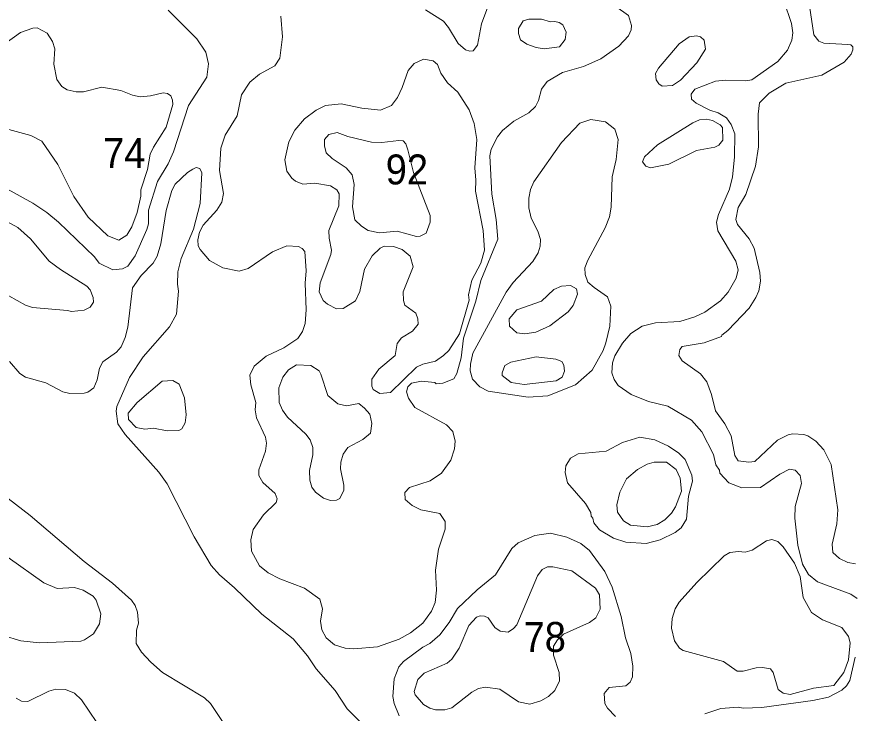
# Model space of a CAD drawing. Extents: x 673.6 to 698.9, y 7012 to 7040.1.
# Drawn here: x 682.608 to 684.841, y 7024.299 to 7026.159 of the extents above; entities that cross this region are included whole.
import ezdxf

# ---------------------------------------------------------------- set-up
doc = ezdxf.new("R2010")
doc.units = 0
doc.header["$LTSCALE"] = 0.032
doc.layers.add('2', color=7, linetype='Continuous', lineweight=13)
doc.layers.add('21', color=7, linetype='Continuous')

msp = doc.modelspace()

# ---------------------------------------------------------------- linework, layer by layer
at = {"layer": '2'}
for points in [[(684.165, 7026.2356), (684.1685, 7026.2173), (684.1927, 7026.1923), (684.2075, 7026.1863), (684.2412, 7026.1626), (684.2493, 7026.1358)], [(683.6996, 7026.1774), (683.7474, 7026.1473), (683.761, 7026.1302), (683.7865, 7026.0876), (683.8056, 7026.0704), (683.8175, 7026.0668), (683.8262, 7026.0681), (683.8384, 7026.0835), (683.8489, 7026.1402), (683.8764, 7026.2147)], [(684.5547, 7025.9879), (684.5703, 7025.9906), (684.6401, 7026.0392), (684.6657, 7026.0694), (684.6776, 7026.0964), (684.6801, 7026.1164), (684.6767, 7026.141), (684.6563, 7026.2012)], [(684.7246, 7026.1881), (684.7361, 7026.1105), (684.7494, 7026.0938), (684.763, 7026.0888), (684.8267, 7026.0847), (684.8345, 7026.0838), (684.8399, 7026.0785), (684.8405, 7026.0703), (684.8358, 7026.0592), (684.8173, 7026.0379), (684.7569, 7026.0031), (684.6608, 7025.9814), (684.6171, 7025.9552), (684.5913, 7025.9291)], [(683.0124, 7026.1763), (683.0891, 7026.1003), (683.1131, 7026.0648), (683.1195, 7026.0329), (683.1156, 7025.9981), (683.0661, 7025.9218), (683.0263, 7025.7982), (683.0122, 7025.7667), (682.9839, 7025.7195), (682.9601, 7025.6424), (682.9593, 7025.6059), (682.9554, 7025.5907), (682.9244, 7025.5205), (682.9047, 7025.4929), (682.8902, 7025.4858), (682.8647, 7025.4835), (682.8284, 7025.5011), (682.8158, 7025.5176), (682.7194, 7025.6106), (682.6879, 7025.6365), (682.6506, 7025.6612), (682.5751, 7025.7032)], [(683.37, 7025.5403), (683.3599, 7025.5456), (683.329, 7025.5473), (683.2904, 7025.5312), (683.2262, 7025.4869), (683.2016, 7025.4793), (683.1585, 7025.4887), (683.1223, 7025.5078), (683.0972, 7025.5373), (683.0926, 7025.547), (683.0916, 7025.5636), (683.0958, 7025.5834), (683.1057, 7025.6026), (683.1419, 7025.6422), (683.1557, 7025.6641), (683.1598, 7025.6871), (683.1492, 7025.7489), (683.1532, 7025.8084), (683.1647, 7025.8429), (683.196, 7025.8942), (683.2078, 7025.9507), (683.2301, 7025.984), (683.256, 7026.0056), (683.2972, 7026.028), (683.3103, 7026.0485), (683.3177, 7026.1058), (683.3134, 7026.161)], [(682.567, 7025.8637), (682.6457, 7025.8423), (682.675, 7025.8268), (682.7173, 7025.7648), (682.7605, 7025.6789), (682.7988, 7025.624), (682.8512, 7025.5741), (682.8801, 7025.5623), (682.902, 7025.5756), (682.9151, 7025.598), (682.9297, 7025.6365), (682.9396, 7025.6802), (682.9388, 7025.697), (682.9571, 7025.751), (682.9644, 7025.7923), (682.9726, 7025.8104), (683.0066, 7025.8645), (683.0243, 7025.9245), (683.0241, 7025.9359), (683.0189, 7025.9481), (683.01, 7025.9542), (682.999, 7025.9559), (682.9646, 7025.9477), (682.9377, 7025.9452), (682.9169, 7025.9497), (682.8854, 7025.9623), (682.8351, 7025.9706), (682.7865, 7025.9583), (682.7663, 7025.9585), (682.7427, 7025.9639), (682.7286, 7025.9731), (682.7152, 7025.9915), (682.707, 7026.0325), (682.7095, 7026.0733), (682.7037, 7026.093), (682.6892, 7026.115), (682.6621, 7026.1291), (682.6512, 7026.1283), (682.6179, 7026.1168), (682.5795, 7026.0896)], [(684.2493, 7026.1358), (684.248, 7026.1244), (684.241, 7026.1084), (684.2153, 7026.0802), (684.1676, 7026.0464), (684.1207, 7026.0262), (684.0654, 7026.01), (684.0243, 7025.9859), (684.0088, 7025.9653), (684.0012, 7025.935), (683.9933, 7025.919), (683.9749, 7025.9024), (683.935, 7025.8806), (683.9047, 7025.855), (683.8918, 7025.8388), (683.8743, 7025.8054), (683.8707, 7025.788), (683.8764, 7025.6854), (683.888, 7025.6174), (683.892, 7025.5649), (683.8466, 7025.4547), (683.8338, 7025.3998), (683.8008, 7025.301), (683.7942, 7025.2484), (683.7831, 7025.2067), (683.7753, 7025.1918), (683.7452, 7025.1805), (683.7279, 7025.1793), (683.7241, 7025.1825), (683.6888, 7025.1858), (683.6622, 7025.1809), (683.6517, 7025.1706), (683.6489, 7025.1573), (683.6535, 7025.1406), (683.6708, 7025.1155), (683.7551, 7025.0697), (683.7719, 7025.0518), (683.7786, 7025.0256), (683.7762, 7025.0054), (683.7668, 7024.9749), (683.7422, 7024.9407), (683.7113, 7024.92), (683.6569, 7024.9018), (683.6437, 7024.8888), (683.6449, 7024.8704), (683.6633, 7024.8536), (683.6864, 7024.8422), (683.7372, 7024.8325), (683.7515, 7024.8116), (683.7514, 7024.7907), (683.7343, 7024.7375), (683.7261, 7024.6813), (683.7285, 7024.628), (683.7247, 7024.5954), (683.7155, 7024.5716), (683.6925, 7024.5402), (683.6592, 7024.5142), (683.6289, 7024.4967), (683.5713, 7024.4769), (683.5076, 7024.471), (683.485, 7024.4734), (683.4564, 7024.4822), (683.4341, 7024.5008), (683.4223, 7024.5223), (683.4188, 7024.5453), (683.4244, 7024.5781), (683.4174, 7024.6037), (683.3759, 7024.6336), (683.3105, 7024.6582), (683.2796, 7024.6742), (683.2563, 7024.6928), (683.2347, 7024.7323), (683.233, 7024.7625), (683.2388, 7024.7901), (683.2671, 7024.8295), (683.3001, 7024.8616), (683.3035, 7024.8717), (683.2982, 7024.8863), (683.2649, 7024.9155), (683.2542, 7024.9338), (683.2544, 7024.9495), (683.2718, 7024.9991), (683.2749, 7025.0205), (683.2724, 7025.0366), (683.2483, 7025.0881), (683.2445, 7025.1096), (683.2461, 7025.1288), (683.233, 7025.1764), (683.2306, 7025.2022), (683.2421, 7025.2263), (683.2735, 7025.2525), (683.3214, 7025.2748), (683.3583, 7025.2997), (683.371, 7025.319), (683.3776, 7025.3404)], [(684.4097, 7025.9389), (684.4082, 7025.9522), (684.4182, 7025.9656), (684.4737, 7025.9872), (684.5002, 7025.9895), (684.5547, 7025.9879)], [(684.8518, 7024.6057), (684.8347, 7024.6171), (684.746, 7024.6505), (684.7215, 7024.6695), (684.7058, 7024.6974), (684.6933, 7024.7483), (684.685, 7024.8199), (684.6864, 7024.8511), (684.7031, 7024.9131), (684.6995, 7024.934), (684.6865, 7024.9481), (684.6709, 7024.9507), (684.6456, 7024.9376), (684.5932, 7024.9024), (684.5434, 7024.9016), (684.509, 7024.9148), (684.4848, 7024.9403), (684.4841, 7024.9485), (684.4747, 7024.9624), (684.4679, 7024.9905), (684.4368, 7025.0511), (684.4092, 7025.0821), (684.3465, 7025.1192), (684.2942, 7025.1315), (684.2481, 7025.1506), (684.2137, 7025.1741), (684.2028, 7025.1905), (684.197, 7025.2085), (684.1986, 7025.2351), (684.2043, 7025.2533), (684.2255, 7025.2875), (684.2471, 7025.3132), (684.2781, 7025.3331), (684.3136, 7025.3419), (684.3784, 7025.3454), (684.4182, 7025.3582), (684.4446, 7025.3704), (684.487, 7025.4004), (684.5071, 7025.4235), (684.5283, 7025.4609), (684.5339, 7025.4837), (684.5273, 7025.506), (684.4796, 7025.5872), (684.4764, 7025.6104), (684.4818, 7025.6312), (684.5107, 7025.6983), (684.519, 7025.7316), (684.5239, 7025.7842), (684.5247, 7025.8465), (684.5157, 7025.8712), (684.5032, 7025.8893), (684.4809, 7025.9026), (684.4587, 7025.9097), (684.4214, 7025.9281), (684.4097, 7025.9389)], [(684.5913, 7025.9291), (684.5873, 7025.8987), (684.588, 7025.8113), (684.5799, 7025.7598), (684.5547, 7025.6846), (684.534, 7025.65)], [(682.589, 7025.2381), (682.6166, 7025.2064), (682.6316, 7025.1968), (682.6852, 7025.1816), (682.7307, 7025.1572), (682.7494, 7025.1533), (682.7876, 7025.1539), (682.7974, 7025.1567), (682.8141, 7025.1682), (682.8225, 7025.1893), (682.8292, 7025.2203), (682.8376, 7025.238), (682.8739, 7025.2632), (682.887, 7025.2773), (682.8978, 7025.3028), (682.9041, 7025.3302), (682.9167, 7025.4349), (682.9405, 7025.4685), (682.9723, 7025.5012), (682.9831, 7025.5196), (682.9922, 7025.5524), (683.0071, 7025.6414), (683.0224, 7025.6955), (683.0311, 7025.7118), (683.064, 7025.7434), (683.0782, 7025.7519), (683.0871, 7025.7561), (683.0969, 7025.7539), (683.102, 7025.742), (683.0974, 7025.6608), (683.0794, 7025.5921), (683.047, 7025.5139), (683.0382, 7025.4781), (683.0367, 7025.4452), (683.0399, 7025.4259), (683.0341, 7025.365), (683.0154, 7025.3308), (682.9451, 7025.2513), (682.9086, 7025.196), (682.8755, 7025.1186), (682.8731, 7025.1058), (682.8781, 7025.0723), (682.8976, 7025.0437), (682.9871, 7024.9429), (683.0094, 7024.9119), (683.0816, 7024.7704), (683.1266, 7024.694), (683.1494, 7024.6686), (683.1895, 7024.6344), (683.2626, 7024.5639), (683.3455, 7024.498), (683.3838, 7024.453), (683.4069, 7024.4178)], [(684.534, 7025.65), (684.528, 7025.6181), (684.5321, 7025.6044), (684.5632, 7025.5657), (684.5769, 7025.5413), (684.5922, 7025.476), (684.5938, 7025.453), (684.5891, 7025.4271), (684.5814, 7025.4094), (684.5631, 7025.3812), (684.5064, 7025.3211), (684.4904, 7025.3091), (684.4898, 7025.3056), (684.4431, 7025.2885), (684.3843, 7025.2786), (684.3781, 7025.2702), (684.3753, 7025.2541), (684.3845, 7025.24), (684.4338, 7025.2052), (684.45, 7025.1842), (684.4629, 7025.1505), (684.4732, 7025.1066), (684.4987, 7025.0721), (684.5155, 7025.0402), (684.5247, 7024.9874), (684.5336, 7024.9737), (684.5621, 7024.9698), (684.5785, 7024.9713), (684.6388, 7025.0286), (684.6675, 7025.0424), (684.6801, 7025.0453), (684.709, 7025.0437), (684.7196, 7025.0402), (684.7409, 7025.0256), (684.7631, 7025.0025), (684.782, 7024.9639), (684.8003, 7024.8423), (684.7977, 7024.8049), (684.7845, 7024.7511), (684.787, 7024.7284), (684.8044, 7024.7122), (684.8271, 7024.7016), (684.8474, 7024.6986)], [(682.5833, 7025.6114), (682.6109, 7025.5967), (682.6449, 7025.5661), (682.6945, 7025.5066), (682.7246, 7025.484), (682.7949, 7025.4397), (682.8039, 7025.4299), (682.8122, 7025.409), (682.8131, 7025.3973), (682.8042, 7025.3835), (682.788, 7025.3757), (682.7543, 7025.3716), (682.7437, 7025.3749), (682.6501, 7025.3823), (682.6312, 7025.3886), (682.5866, 7025.4142)], [(683.3776, 7025.3404), (683.381, 7025.3761), (683.3776, 7025.4474), (683.3808, 7025.481), (683.3769, 7025.532), (683.37, 7025.5403)], [(683.1646, 7024.2666), (683.1256, 7024.3252), (683.1095, 7024.3406), (682.9974, 7024.4078), (682.9657, 7024.4358), (682.9412, 7024.4626), (682.9269, 7024.4851), (682.9273, 7024.5215), (682.933, 7024.5399), (682.9306, 7024.5692), (682.9244, 7024.5866), (682.9143, 7024.6013), (682.8635, 7024.6465), (682.7879, 7024.7049), (682.644, 7024.8273), (682.5846, 7024.8727)], [(684.2063, 7024.2906), (684.185, 7024.3132), (684.1776, 7024.3256), (684.1764, 7024.3521), (684.1895, 7024.368), (684.2343, 7024.3723), (684.2458, 7024.3826), (684.2519, 7024.3961), (684.2527, 7024.4249), (684.2472, 7024.4587), (684.233, 7024.5009), (684.2216, 7024.5575), (684.1974, 7024.6363), (684.1782, 7024.6775), (684.1369, 7024.7339), (684.1142, 7024.7525), (684.0763, 7024.7695), (684.0329, 7024.78), (683.9908, 7024.7739), (683.9465, 7024.754), (683.9294, 7024.739), (683.8857, 7024.6687), (683.8368, 7024.6284), (683.7846, 7024.5788), (683.762, 7024.5413), (683.7373, 7024.5085), (683.7107, 7024.4859), (683.6921, 7024.4756), (683.6403, 7024.4377), (683.628, 7024.4232), (683.616, 7024.3908), (683.6123, 7024.3438), (683.6159, 7024.325), (683.6289, 7024.2922)], [(682.585, 7024.7154), (682.68, 7024.6476), (682.7162, 7024.6328), (682.7618, 7024.6352), (682.7851, 7024.6278), (682.8118, 7024.6116), (682.8202, 7024.6008), (682.8327, 7024.5649), (682.8285, 7024.538), (682.8131, 7024.5112), (682.7887, 7024.4949), (682.7787, 7024.4915), (682.669, 7024.4874), (682.6187, 7024.4924), (682.5721, 7024.5069)], [(684.4448, 7024.2974), (684.4875, 7024.3122), (684.5338, 7024.3154), (684.5475, 7024.3124), (684.5968, 7024.3143), (684.7334, 7024.3329), (684.7748, 7024.3425), (684.8108, 7024.3607), (684.8229, 7024.3724), (684.832, 7024.3871), (684.8461, 7024.4488)], [(683.4069, 7024.4178), (683.4577, 7024.3597), (683.4897, 7024.3113), (683.5591, 7024.2409), (683.5731, 7024.2116), (683.5839, 7024.1784)], [(682.6063, 7024.3393), (682.6205, 7024.3314), (682.6372, 7024.3304), (682.6938, 7024.3586), (682.7125, 7024.3632), (682.7385, 7024.363), (682.7618, 7024.3528), (682.7808, 7024.3348), (682.8218, 7024.2748)]]:
    msp.add_lwpolyline(points, dxfattribs=at)
for points in [[(683.9699, 7026.0858), (683.9532, 7026.0977), (683.9476, 7026.1143), (683.9474, 7026.1281), (683.9599, 7026.1482), (683.975, 7026.153), (684.0092, 7026.153), (684.0332, 7026.1451), (684.0448, 7026.1461), (684.0557, 7026.144), (684.0663, 7026.1379), (684.0744, 7026.1177), (684.0721, 7026.0984), (684.0571, 7026.0784), (684.0156, 7026.0737), (683.9944, 7026.0767)], [(684.3307, 7025.9733), (684.3222, 7025.9795), (684.3147, 7025.9909), (684.3137, 7026.0072), (684.3215, 7026.0215), (684.376, 7026.0871), (684.4034, 7026.1053), (684.4229, 7026.1077), (684.4333, 7026.1057), (684.4436, 7026.0963), (684.4467, 7026.0729), (684.4237, 7026.0356), (684.3801, 7025.9896), (684.3587, 7025.9756)], [(683.5124, 7025.4006), (683.5236, 7025.4252), (683.5363, 7025.4849), (683.5564, 7025.5209), (683.578, 7025.5408), (683.5889, 7025.5464), (683.6135, 7025.5457), (683.6371, 7025.538), (683.6584, 7025.5197), (683.6667, 7025.4911), (683.6398, 7025.4241), (683.6401, 7025.4015), (683.6436, 7025.3892), (683.6733, 7025.3676), (683.6791, 7025.3525), (683.6792, 7025.3382), (683.6642, 7025.3197), (683.6355, 7025.3015), (683.6235, 7025.2866), (683.6182, 7025.2547), (683.5746, 7025.2176), (683.5562, 7025.191), (683.556, 7025.1728), (683.5597, 7025.1635), (683.5773, 7025.1531), (683.6057, 7025.1555), (683.6749, 7025.2234), (683.692, 7025.2317), (683.7259, 7025.2397), (683.7476, 7025.2544), (683.7611, 7025.2678), (683.7903, 7025.312), (683.8155, 7025.4027), (683.8141, 7025.4167), (683.823, 7025.4559), (683.8468, 7025.5015), (683.8567, 7025.536), (683.8534, 7025.5885), (683.8324, 7025.6931), (683.8337, 7025.7224), (683.8305, 7025.7557), (683.8361, 7025.8317), (683.8292, 7025.8744), (683.8158, 7025.9102), (683.7851, 7025.9574), (683.758, 7025.9824), (683.7405, 7026.0085), (683.7312, 7026.0319), (683.7195, 7026.0415), (683.6943, 7026.0454), (683.6686, 7026.0339), (683.6531, 7026.0157), (683.6372, 7025.9698), (683.6241, 7025.9436), (683.6086, 7025.9224), (683.5794, 7025.9098), (683.5292, 7025.9145), (683.4742, 7025.9262), (683.4322, 7025.9217), (683.4074, 7025.9094), (683.3763, 7025.8863), (683.3506, 7025.8565), (683.3342, 7025.8254), (683.3235, 7025.7767), (683.3287, 7025.7471), (683.3421, 7025.7277), (683.3517, 7025.7198), (683.3714, 7025.7118), (683.4039, 7025.715), (683.4455, 7025.7077), (683.4626, 7025.6966), (683.4687, 7025.6861), (683.468, 7025.6543), (683.441, 7025.5885), (683.4417, 7025.5675), (683.4482, 7025.5359), (683.4466, 7025.5243), (683.4183, 7025.4483), (683.4155, 7025.4242), (683.4259, 7025.4014), (683.4375, 7025.3917), (683.4618, 7025.379), (683.4795, 7025.3801)], [(684.1109, 7025.8753), (684.1403, 7025.885), (684.1802, 7025.8787), (684.2044, 7025.8592), (684.2133, 7025.8317), (684.2084, 7025.7775), (684.1976, 7025.732), (684.1952, 7025.6502), (684.1903, 7025.6247), (684.1789, 7025.5952), (684.1325, 7025.509), (684.1247, 7025.4882), (684.1254, 7025.4705), (684.133, 7025.4507), (684.1494, 7025.4358), (684.1853, 7025.4115), (684.1936, 7025.3863), (684.1912, 7025.3325), (684.1811, 7025.2882), (684.1731, 7025.2679), (684.1443, 7025.2153), (684.0997, 7025.1762), (684.0257, 7025.1464), (683.9731, 7025.1432), (683.8667, 7025.1589), (683.8439, 7025.1705), (683.8248, 7025.1916), (683.8181, 7025.2133), (683.819, 7025.2318), (683.8259, 7025.2609), (683.9149, 7025.4236), (683.9336, 7025.4494), (683.9859, 7025.5058), (684, 7025.5284), (684.0053, 7025.5467), (684.0062, 7025.564), (683.9994, 7025.5867), (683.9812, 7025.6208), (683.9751, 7025.6486), (683.9751, 7025.6742), (683.9798, 7025.698), (683.9881, 7025.718), (684.0621, 7025.8235)], [(684.4226, 7025.802), (684.472, 7025.8109), (684.4826, 7025.8158), (684.4927, 7025.8293), (684.4919, 7025.8629), (684.4856, 7025.8706), (684.4657, 7025.8821), (684.4491, 7025.8859), (684.4306, 7025.8836), (684.4132, 7025.8758), (684.3186, 7025.8169), (684.2839, 7025.7854), (684.2784, 7025.7715), (684.2877, 7025.7602), (684.3003, 7025.7554), (684.3491, 7025.7658)], [(683.7114, 7025.6287), (683.712, 7025.6103), (683.7012, 7025.5812), (683.6851, 7025.5731), (683.6748, 7025.5721), (683.6233, 7025.5868), (683.5762, 7025.5819), (683.5461, 7025.5885), (683.5283, 7025.5998), (683.5105, 7025.6165), (683.5042, 7025.6514), (683.5092, 7025.7112), (683.5038, 7025.737), (683.4872, 7025.7559), (683.4502, 7025.7809), (683.4336, 7025.796), (683.4293, 7025.8148), (683.4295, 7025.8317), (683.4411, 7025.845), (683.4636, 7025.8499), (683.4922, 7025.8391), (683.5552, 7025.8244), (683.5828, 7025.8236), (683.6278, 7025.8289), (683.6394, 7025.8276), (683.6466, 7025.8199), (683.6519, 7025.8041), (683.6669, 7025.743)], [(684.0934, 7025.3878), (684.1054, 7025.418), (684.1024, 7025.4328), (684.0865, 7025.4415), (684.0621, 7025.4397), (684.0422, 7025.4305), (684.0089, 7025.3993), (683.9433, 7025.3768), (683.9225, 7025.3523), (683.9233, 7025.3324), (683.9433, 7025.3152), (683.9647, 7025.3125), (683.9938, 7025.3167), (684.0309, 7025.3338), (684.0797, 7025.371)], [(684.0476, 7025.245), (684.063, 7025.2389), (684.0687, 7025.229), (684.0702, 7025.2128), (684.0637, 7025.1966), (684.0483, 7025.1865), (683.9623, 7025.177), (683.9283, 7025.1823), (683.9043, 7025.2013), (683.9036, 7025.2084), (683.9111, 7025.2277), (683.9269, 7025.2363), (683.995, 7025.2509)], [(683.3799, 7025.0442), (683.3308, 7025.0898), (683.3178, 7025.1083), (683.3085, 7025.1287), (683.3078, 7025.1684), (683.3183, 7025.197), (683.3338, 7025.216), (683.355, 7025.2293), (683.3932, 7025.2277), (683.415, 7025.2132), (683.4202, 7025.2051), (683.4387, 7025.148), (683.4656, 7025.1255), (683.4881, 7025.1202), (683.5211, 7025.1266), (683.5365, 7025.1141), (683.5502, 7025.0976), (683.5559, 7025.0731), (683.5525, 7025.0471), (683.5316, 7025.0299), (683.4919, 7025.0091), (683.4794, 7024.9907), (683.473, 7024.9693), (683.4721, 7024.9517), (683.4811, 7024.9085), (683.4811, 7024.8949), (683.4704, 7024.873), (683.4618, 7024.868), (683.4455, 7024.8671), (683.4272, 7024.8734), (683.4053, 7024.8897), (683.3957, 7024.903), (683.3907, 7024.9216), (683.3891, 7024.9474), (683.398, 7024.9895), (683.3982, 7025.0093), (683.3916, 7025.0296)], [(682.9728, 7025.0609), (683.0098, 7025.0534), (683.0405, 7025.0544), (683.0486, 7025.0591), (683.0572, 7025.0744), (683.0604, 7025.0962), (683.0555, 7025.1411), (683.0416, 7025.1781), (683.0246, 7025.1878), (682.9958, 7025.1864), (682.9297, 7025.1291), (682.9054, 7025.1003), (682.9064, 7025.0838), (682.9266, 7025.0619), (682.95, 7025.0577)], [(684.4016, 7024.8789), (684.4121, 7024.9193), (684.4105, 7024.9352), (684.3923, 7024.9765), (684.3755, 7024.9941), (684.3478, 7025.0126), (684.3119, 7025.0297), (684.2712, 7025.0362), (684.2248, 7025.0226), (684.1818, 7024.9992), (684.1065, 7024.9919), (684.0862, 7024.9807), (684.0737, 7024.9603), (684.072, 7024.9423), (684.0779, 7024.9147), (684.126, 7024.8591), (684.1409, 7024.8353), (684.1412, 7024.8254), (684.1459, 7024.8198), (684.149, 7024.8076), (684.1637, 7024.7894), (684.2011, 7024.767), (684.2343, 7024.7558), (684.2885, 7024.7528), (684.3258, 7024.7621), (684.3658, 7024.7822), (684.3817, 7024.794), (684.3956, 7024.8172)], [(684.3688, 7024.9501), (684.3424, 7024.9698), (684.3096, 7024.9696), (684.2909, 7024.9641), (684.265, 7024.9504), (684.2361, 7024.925), (684.2182, 7024.8897), (684.2101, 7024.8559), (684.2118, 7024.8362), (684.2281, 7024.8129), (684.2461, 7024.8018), (684.2911, 7024.7971), (684.3176, 7024.8032), (684.3385, 7024.8155), (684.3561, 7024.8331), (684.3669, 7024.8501), (684.3823, 7024.8921), (684.3794, 7024.9271)], [(684.7588, 7024.549), (684.7295, 7024.5681), (684.7074, 7024.6084), (684.6991, 7024.6645), (684.6846, 7024.7004), (684.6538, 7024.7437), (684.6395, 7024.7578), (684.6235, 7024.7633), (684.6097, 7024.7595), (684.5716, 7024.7344), (684.5522, 7024.7298), (684.5348, 7024.7314), (684.5115, 7024.7282), (684.4963, 7024.7194), (684.4235, 7024.6482), (684.3767, 7024.5956), (684.3661, 7024.5782), (684.3574, 7024.5525), (684.3556, 7024.5262), (684.3638, 7024.4924), (684.3773, 7024.473), (684.3873, 7024.467), (684.4944, 7024.4372), (684.5317, 7024.4117), (684.5474, 7024.4118), (684.5816, 7024.4207), (684.5986, 7024.4216), (684.6204, 7024.4176), (684.6274, 7024.4084), (684.6407, 7024.3625), (684.6541, 7024.3528), (684.6724, 7024.3494), (684.7353, 7024.3664), (684.7892, 7024.3733), (684.8161, 7024.4079), (684.8284, 7024.4415), (684.8329, 7024.4877), (684.8285, 7024.5044), (684.8108, 7024.5284)], [(684.0572, 7024.3858), (684.0563, 7024.4084), (684.0409, 7024.4541), (684.041, 7024.4788), (684.0515, 7024.495), (684.0673, 7024.5104), (684.1372, 7024.5413), (684.1542, 7024.5542), (684.1658, 7024.5768), (684.1641, 7024.6152), (684.1528, 7024.6332), (684.0898, 7024.6795), (684.0391, 7024.6903), (684.0251, 7024.6904), (684.011, 7024.6834), (683.9981, 7024.6666), (683.9432, 7024.5354), (683.9341, 7024.5254), (683.9195, 7024.5162), (683.8982, 7024.5185), (683.8846, 7024.5279), (683.8662, 7024.5541), (683.8571, 7024.5586), (683.8456, 7024.5596), (683.8358, 7024.556), (683.8148, 7024.5333), (683.7887, 7024.473), (683.7691, 7024.4436), (683.7572, 7024.4332), (683.6959, 7024.4062), (683.6787, 7024.389), (683.6687, 7024.3576), (683.6714, 7024.3483), (683.6939, 7024.323), (683.711, 7024.3125), (683.7256, 7024.3082), (683.7504, 7024.3087), (683.7696, 7024.3141), (683.823, 7024.3558), (683.841, 7024.3655), (683.8593, 7024.369), (683.8975, 7024.3633), (683.9477, 7024.33), (683.978, 7024.3231), (684.0075, 7024.3325), (684.0279, 7024.3438), (684.0449, 7024.3601)]]:
    msp.add_lwpolyline(points, close=True, dxfattribs=at)

# ---------------------------------------------------------------- texts
at = {"layer": '21', "width": 0.95}
for s, p in [('74', (682.8385, 7025.7552)), ('92', (683.5929, 7025.7113)), ('78', (683.961, 7024.463))]:
    msp.add_text(s, height=0.08, dxfattribs=at).set_placement(p)

doc.saveas('drawing.dxf')
